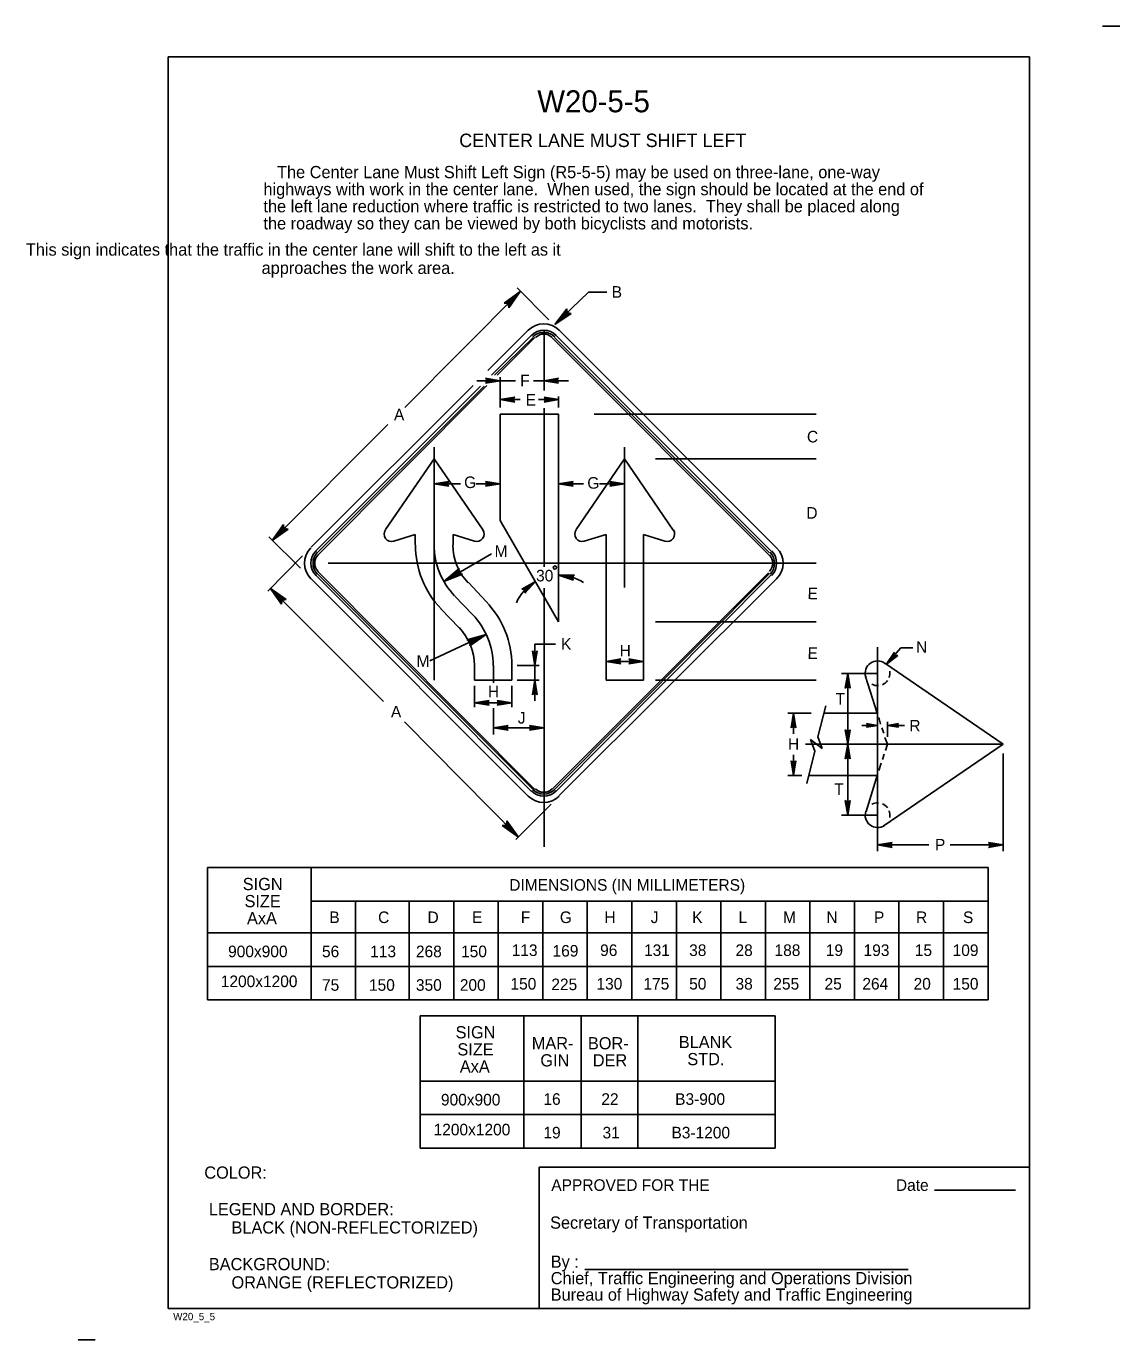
# Model space of a CAD drawing. Extents: x -0.029 to 0.195, y -0.006 to 0.263.
import ezdxf

# ---------------------------------------------------------------- set-up
doc = ezdxf.new("R2010")
doc.units = 0
for name, color, linetype in [('1', 7, 'Continuous'), ('2', 7, 'Continuous'), ('3', 7, 'Continuous')]:
    doc.layers.add(name, color=color, linetype=linetype)

# ---------------------------------------------------------------- blocks, each defined once
blk = doc.blocks.new('RARROW')
at = {"layer": '3'}
for p, q in [((-2.156, 0.28500000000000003), (-2.2665, 0.384625)), ((-2.2665, 0.384625), (0, 0)), ((0, 0), (-2.2665, -0.379125)), ((-2.156, 0.28500000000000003), (-2.075625, 0.12075)), ((0, 0), (-2.156, 0.28500000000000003)), ((-2.14975, -0.2705), (0, 0)), ((-2.075625, 0.12075), (0, 0)), ((0, 0), (-2.074, -0.108)), ((-2.2665, -0.379125), (-2.14975, -0.2705)), ((-2.074, -0.108), (-2.14975, -0.2705))]:
    blk.add_line(p, q, dxfattribs=at)

msp = doc.modelspace()

# ---------------------------------------------------------------- linework, layer by layer
at = {"layer": '1'}
for p, q in [((0.195, 0.26275), (0.1915, 0.26275)), ((0.1765, 0.2565), (0, 0.2565)), ((0, 0.2565), (0, 0)), ((0.1765, 0), (0.1765, 0.2565)), ((0.077, 0.20025), (0.077, 0.18812500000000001)), ((0.0795, 0.199375), (0.1235, 0.15525)), ((0.080125, 0.2005), (0.124625, 0.155875)), ((0.078625, 0.199), (0.123125, 0.154375)), ((0.079125, 0.199), (0.12325, 0.154875)), ((0.068, 0.18325), (0.08, 0.18325)), ((0.068, 0.18325), (0.068, 0.1615)), ((0.077, 0.1845), (0.077, 0.152)), ((0.08, 0.18325), (0.08, 0.14075000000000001)), ((0.0545, 0.12875), (0.0545, 0.1765)), ((0.0935, 0.14775), (0.0935, 0.1765)), ((0.0445, 0.15962500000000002), (0.0545, 0.174125)), ((0.0645, 0.1595), (0.0545, 0.174125)), ((0.083625, 0.15962500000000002), (0.0935, 0.174125)), ((0.10350000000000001, 0.1595), (0.0935, 0.174125)), ((0.068, 0.1615), (0.08, 0.14075000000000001)), ((0.04625, 0.15725), (0.050625, 0.15862500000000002)), ((0.050625, 0.1565), (0.050625, 0.15862500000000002)), ((0.06275, 0.15725), (0.058375, 0.15862500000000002)), ((0.058375, 0.1565), (0.058375, 0.15862500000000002)), ((0.08525, 0.15725), (0.08975, 0.15862500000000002)), ((0.08975, 0.12875), (0.08975, 0.15862500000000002)), ((0.10175000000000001, 0.15725), (0.097375, 0.15862500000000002)), ((0.097375, 0.12875), (0.097375, 0.15862500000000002)), ((0.030625, 0.151), (0.075125, 0.106375)), ((0.03275, 0.15275), (0.129125, 0.15275)), ((0.02925, 0.1495), (0.07375, 0.105)), ((0.03025, 0.15025), (0.074375, 0.106)), ((0.0305, 0.150625), (0.07475, 0.106375)), ((0.0615, 0.14875), (0.065125, 0.144875)), ((0.058750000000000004, 0.146), (0.062375, 0.14225000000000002)), ((0.077, 0.147625), (0.077, 0.094625)), ((0.055875, 0.143375), (0.059625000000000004, 0.1395)), ((0.145375, 0.1355), (0.145375, 0.097125)), ((0.146875, 0.13225), (0.171125, 0.115625)), ((0.06275, 0.13175), (0.06275, 0.12875)), ((0.066625, 0.13175), (0.066625, 0.12825)), ((0.07037500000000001, 0.13175), (0.07037500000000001, 0.12875)), ((0.142875, 0.1295), (0.14525, 0.122)), ((0.066625, 0.123), (0.066625, 0.11762500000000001)), ((0.13475, 0.1235), (0.133125, 0.117125)), ((0.134375, 0.122), (0.14525, 0.122)), ((0.145625, 0.121125), (0.146, 0.11975000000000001)), ((0.14625, 0.11900000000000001), (0.146625, 0.11787500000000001)), ((0.1325, 0.11425), (0.131625, 0.116625)), ((0.131625, 0.116625), (0.134, 0.11475)), ((0.134, 0.11475), (0.133125, 0.117125)), ((0.146875, 0.117), (0.147375, 0.115625)), ((0.130625, 0.115625), (0.171125, 0.115625)), ((0.1325, 0.11425), (0.130875, 0.107625)), ((0.146375, 0.1125), (0.14675, 0.113625)), ((0.14675, 0.099), (0.171125, 0.115625)), ((0.147, 0.114375), (0.147375, 0.115625)), ((0.145625, 0.11025), (0.146125, 0.11175)), ((0.13125, 0.10925), (0.14525, 0.10925)), ((0.14300000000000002, 0.10187500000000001), (0.14525, 0.10925)), ((0.076, 0.029), (0.1765, 0.029)), ((0.076, 0.029), (0.076, 0)), ((0.157, 0.02425), (0.173625, 0.02425)), ((0.085375, 0.008), (0.151625, 0.008)), ((0, 0), (0.1765, 0)), ((-0.015, -0.0063750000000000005), (-0.0185, -0.0063750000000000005))]:
    msp.add_line(p, q, dxfattribs=at)
for centre, radius, start, end in [((0.045770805, 0.15869167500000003), 0.00152, 143.78869166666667, 286.41078333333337), ((0.063210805, 0.15869167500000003), 0.00152, 251.56804722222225, 34.022558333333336), ((0.084810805, 0.15869167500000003), 0.00152, 143.78869166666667, 286.41078333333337), ((0.102250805, 0.15869167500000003), 0.00152, 251.56804722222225, 34.022558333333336), ((0.069530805, 0.15645167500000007), 0.01888, 180, 223.86679444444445), ((0.069530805, 0.15645167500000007), 0.015040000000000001, 180, 223.86679444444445), ((0.069530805, 0.15645167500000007), 0.011200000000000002, 180, 223.86686666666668), ((0.051530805, 0.13177167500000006), 0.01888, 0, 43.86675), ((0.051530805, 0.13177167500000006), 0.015040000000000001, 0, 43.866794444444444), ((0.051530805, 0.13177167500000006), 0.011200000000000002, 0, 43.866794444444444), ((0.1453589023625, 0.13016981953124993), 0.0025326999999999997, 53.788691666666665, 196.41078333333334), ((0.1453589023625, 0.13016981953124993), 0.0025326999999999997, 340.1148361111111, 10.505063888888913), ((0.1453589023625, 0.13016981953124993), 0.0025326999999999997, 242.24145833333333, 273.7748277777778), ((0.1453589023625, 0.13016981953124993), 0.0025326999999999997, 292.9782916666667, 323.56914166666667), ((0.1453589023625, 0.10111041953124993), 0.0025326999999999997, 86.22517222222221, 117.75854166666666), ((0.1453589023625, 0.10111041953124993), 0.0025326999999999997, 36.43085833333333, 67.02170833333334), ((0.1453589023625, 0.10111041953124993), 0.0025326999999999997, 161.56804722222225, 304.02255833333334), ((0.1453589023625, 0.10111041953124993), 0.0025326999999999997, 349.4949361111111, 19.88516388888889)]:
    msp.add_arc(centre, radius, start, end, dxfattribs=at)
at = {"layer": '3'}
for p, q in [((0.0485, 0.184625), (0.072125, 0.208375)), ((0.078, 0.202625), (0.07150000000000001, 0.209125)), ((0.078, 0.202625), (0.07150000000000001, 0.209125)), ((0.07925, 0.201625), (0.08612500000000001, 0.20825)), ((0.08612500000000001, 0.20825), (0.089875, 0.20825)), ((0.0655, 0.19225), (0.07375, 0.2005)), ((0.06625, 0.19125), (0.074375, 0.199375)), ((0.066875, 0.19125), (0.07475, 0.199)), ((0.067375, 0.19125), (0.075125, 0.199)), ((0.02925, 0.156), (0.0625, 0.18912500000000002)), ((0.03025, 0.15525), (0.064, 0.189)), ((0.0305, 0.154875), (0.06475, 0.189)), ((0.030625, 0.154375), (0.06525, 0.18912500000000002)), ((0.06325, 0.19012500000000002), (0.068, 0.19012500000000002)), ((0.068, 0.184625), (0.068, 0.19087500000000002)), ((0.07112500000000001, 0.19012500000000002), (0.068, 0.19012500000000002)), ((0.077, 0.19012500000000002), (0.074875, 0.19012500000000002)), ((0.077, 0.19087500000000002), (0.077, 0.18812500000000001)), ((0.077, 0.19012500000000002), (0.082, 0.19012500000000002)), ((0.072125, 0.18625), (0.068, 0.18625)), ((0.08, 0.18625), (0.075875, 0.18625)), ((0.08, 0.184625), (0.08, 0.186875)), ((0.08725000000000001, 0.18325), (0.13275, 0.18325)), ((0.045, 0.181125), (0.02125, 0.15737500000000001)), ((0.099875, 0.174125), (0.13275, 0.174125)), ((0.0545, 0.169), (0.059875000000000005, 0.169)), ((0.063, 0.169), (0.068, 0.169)), ((0.085125, 0.169), (0.08, 0.169)), ((0.0935, 0.169), (0.088375, 0.169)), ((0.027125, 0.15175), (0.020625, 0.15812500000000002)), ((0.0275, 0.15425), (0.020375, 0.147)), ((0.06625, 0.154625), (0.0565, 0.149)), ((0.07875, 0.1065), (0.123, 0.15075)), ((0.129125, 0.15275), (0.13275, 0.15275)), ((0.079125, 0.106375), (0.12325, 0.150625)), ((0.0795, 0.106), (0.1235, 0.15025)), ((0.080125, 0.105125), (0.124625, 0.1495)), ((0.044125, 0.124375), (0.020875, 0.147625)), ((0.099875, 0.14075000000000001), (0.13275, 0.14075000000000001)), ((0.053625, 0.13275), (0.065125, 0.138125)), ((0.075125, 0.136125), (0.075125, 0.13175)), ((0.075125, 0.136125), (0.079375, 0.136125)), ((0.147125, 0.132), (0.150125, 0.135375)), ((0.152625, 0.135375), (0.150125, 0.135375)), ((0.08975, 0.132625), (0.097375, 0.132625)), ((0.07150000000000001, 0.13175), (0.076, 0.13175)), ((0.075125, 0.13175), (0.075125, 0.12875)), ((0.138, 0.130125), (0.145375, 0.130125)), ((0.13925, 0.115625), (0.13925, 0.130125)), ((0.07037500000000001, 0.12875), (0.06275, 0.12875)), ((0.06275, 0.12762500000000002), (0.06275, 0.12325)), ((0.07037500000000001, 0.12762500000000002), (0.07037500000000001, 0.12325)), ((0.07150000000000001, 0.12875), (0.076, 0.12875)), ((0.075125, 0.12875), (0.075125, 0.1245)), ((0.08975, 0.12875), (0.097375, 0.12875)), ((0.099875, 0.12875), (0.13275, 0.12875)), ((0.06275, 0.124125), (0.07037500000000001, 0.124125)), ((0.127, 0.122), (0.13175, 0.122)), ((0.128125, 0.11775000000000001), (0.128125, 0.122)), ((0.048375, 0.12025), (0.07175000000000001, 0.096625)), ((0.066625, 0.11900000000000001), (0.077, 0.11900000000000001)), ((0.145375, 0.11950000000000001), (0.142125, 0.11950000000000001)), ((0.147375, 0.117125), (0.147375, 0.12025)), ((0.150875, 0.11950000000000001), (0.147375, 0.11950000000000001)), ((0.128125, 0.1135), (0.128125, 0.10925)), ((0.13925, 0.115625), (0.13925, 0.101125)), ((0.171125, 0.09375), (0.171125, 0.11375)), ((0.127, 0.10925), (0.129875, 0.10925)), ((0.0785, 0.10337500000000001), (0.07125000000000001, 0.096125)), ((0.138, 0.101125), (0.145375, 0.101125)), ((0.145375, 0.09375), (0.145375, 0.097125)), ((0.145375, 0.095), (0.155875, 0.095)), ((0.16025, 0.095), (0.171125, 0.095)), ((0.008, 0.090375), (0.168, 0.090375)), ((0.008, 0.090375), (0.008, 0.06325)), ((0.02925, 0.090375), (0.02925, 0.06325)), ((0.168, 0.090375), (0.168, 0.06325)), ((0.168, 0.0835), (0.02925, 0.0835)), ((0.038375, 0.0835), (0.038375, 0.06325)), ((0.049375, 0.0835), (0.049375, 0.06325)), ((0.0585, 0.0835), (0.0585, 0.06325)), ((0.067625, 0.0835), (0.067625, 0.06325)), ((0.07675, 0.0835), (0.07675, 0.06325)), ((0.085875, 0.0835), (0.085875, 0.06325)), ((0.095, 0.0835), (0.095, 0.06325)), ((0.104125, 0.0835), (0.104125, 0.06325)), ((0.11325, 0.0835), (0.11325, 0.06325)), ((0.122375, 0.0835), (0.122375, 0.06325)), ((0.1315, 0.0835), (0.1315, 0.06325)), ((0.140625, 0.0835), (0.140625, 0.06325)), ((0.14975, 0.0835), (0.14975, 0.06325)), ((0.15887500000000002, 0.0835), (0.15887500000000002, 0.06325)), ((0.008, 0.077), (0.168, 0.077)), ((0.008, 0.070125), (0.168, 0.070125)), ((0.008, 0.06325), (0.168, 0.06325)), ((0.051625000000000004, 0.06), (0.124375, 0.06)), ((0.051625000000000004, 0.06), (0.051625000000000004, 0.032875)), ((0.072875, 0.06), (0.072875, 0.032875)), ((0.072875, 0.06), (0.072875, 0.03975)), ((0.084625, 0.06), (0.084625, 0.032875)), ((0.09625, 0.06), (0.09625, 0.032875)), ((0.124375, 0.06), (0.124375, 0.032875)), ((0.051625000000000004, 0.046625), (0.124375, 0.046625)), ((0.051625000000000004, 0.03975), (0.124375, 0.03975)), ((0.051625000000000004, 0.032875), (0.124375, 0.032875))]:
    msp.add_line(p, q, dxfattribs=at)
msp.add_circle((0.0792320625, 0.1518385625), 0.00034737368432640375, dxfattribs=at)
for centre, radius, start, end in [((0.07695602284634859, 0.19727937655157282), 0.0044998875, 45, 135), ((0.07695602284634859, 0.19685512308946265), 0.003599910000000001, 45, 135), ((0.07695602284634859, 0.19685512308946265), 0.0031780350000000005, 45, 135), ((0.07695602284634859, 0.19727937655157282), 0.0023998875, 45, 135), ((0.0324090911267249, 0.15273244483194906), 0.0044998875, 135, 225), ((0.032833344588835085, 0.15273244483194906), 0.003599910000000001, 135, 225), ((0.032833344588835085, 0.15273244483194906), 0.0031780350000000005, 135, 225), ((0.0324090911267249, 0.15273244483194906), 0.0023998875, 135, 225), ((0.12150263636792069, 0.15273276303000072), 0.0023998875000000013, 315, 45), ((0.12107838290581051, 0.15273276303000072), 0.0031780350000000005, 315, 45), ((0.12107838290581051, 0.15273276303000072), 0.003599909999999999, 315, 45), ((0.12150263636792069, 0.15273276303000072), 0.004499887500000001, 315, 45), ((0.08001075, 0.140731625), 0.009504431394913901, 119.99356666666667, 155.97758333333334), ((0.08001075, 0.140731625), 0.009504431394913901, 57.56237777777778, 90), ((0.07695570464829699, 0.108185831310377), 0.004499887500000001, 225.00000000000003, 315), ((0.07695570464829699, 0.1086100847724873), 0.003599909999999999, 225.00000000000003, 315), ((0.07695570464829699, 0.1086100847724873), 0.0031780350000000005, 225.00000000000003, 315), ((0.07695570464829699, 0.108185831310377), 0.0023998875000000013, 225.00000000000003, 315)]:
    msp.add_arc(centre, radius, start, end, dxfattribs=at)

# ---------------------------------------------------------------- block references
for p, xscale, yscale, rotation in [((0.072125, 0.208375), 0.0017647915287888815, 0.0017457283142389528, 44.99999999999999), ((0.07925, 0.201625), 0.0017647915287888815, 0.001745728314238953, -136), ((0.077, 0.19012500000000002), 0.0013235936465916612, 0.0013092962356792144, 180), ((0.068, 0.18625), 0.0013235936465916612, 0.0013092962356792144, 180), ((0.0545, 0.169), 0.0013235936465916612, 0.0013092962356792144, 180), ((0.08, 0.169), 0.0013235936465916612, 0.0013092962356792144, 180), ((0.02125, 0.15737500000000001), 0.0017647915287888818, 0.0017457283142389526, -135.00000000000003), ((0.0565, 0.149), 0.0017647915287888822, 0.0017457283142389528, -148.99999999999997), ((0.08, 0.15025), 0.0014118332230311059, -0.0013965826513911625, 170.99999999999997), ((0.020875, 0.147625), 0.0017647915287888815, 0.0017457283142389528, 135), ((0.07525, 0.149), 0.001411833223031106, 0.0013965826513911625, 39.00000000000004), ((0.065125, 0.138125), 0.001764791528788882, 0.001745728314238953, 25.00000000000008), ((0.075125, 0.13175), 0.0013235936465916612, 0.0013092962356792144, -90.00000000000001), ((0.08975, 0.132625), 0.0013235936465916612, 0.0013092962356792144, 180), ((0.147125, 0.132), 0.0013235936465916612, -0.0013092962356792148, -132.99999999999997), ((0.13925, 0.130125), 0.0013235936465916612, -0.0013092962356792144, 90.00000000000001), ((0.075125, 0.12875), 0.0013235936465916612, -0.0013092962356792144, 90.00000000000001), ((0.06275, 0.124125), 0.0013235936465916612, 0.0013092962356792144, 180), ((0.128125, 0.122), 0.0013235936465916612, -0.0013092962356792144, 90.00000000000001), ((0.066625, 0.11900000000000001), 0.0013235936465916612, 0.0013092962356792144, 180), ((0.13925, 0.115625), 0.0013235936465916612, 0.0013092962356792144, -90.00000000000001), ((0.147375, 0.11950000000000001), 0.000992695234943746, 0.0009819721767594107, 180), ((0.13925, 0.115625), 0.0013235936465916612, -0.0013092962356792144, 90.00000000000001), ((0.128125, 0.10925), 0.0013235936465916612, 0.0013092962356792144, -90.00000000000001), ((0.13925, 0.101125), 0.0013235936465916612, 0.0013092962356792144, -90.00000000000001), ((0.07175000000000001, 0.096625), 0.0017647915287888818, 0.0017457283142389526, -45.00000000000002), ((0.145375, 0.095), 0.0013235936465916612, -0.0013092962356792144, -180)]:
    msp.add_blockref('RARROW', p, dxfattribs=dict(at, xscale=xscale, yscale=yscale, rotation=rotation))
for p, xscale, yscale in [((0.068, 0.19012500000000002), 0.0013235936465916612, -0.0013092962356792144), ((0.08, 0.18625), 0.0013235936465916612, -0.0013092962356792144), ((0.068, 0.169), 0.0013235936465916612, -0.0013092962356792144), ((0.0935, 0.169), 0.0013235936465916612, -0.0013092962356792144), ((0.097375, 0.132625), 0.0013235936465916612, -0.0013092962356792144), ((0.07037500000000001, 0.124125), 0.0013235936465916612, -0.0013092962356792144), ((0.077, 0.11900000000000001), 0.0013235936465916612, -0.0013092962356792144), ((0.145375, 0.11950000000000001), 0.000992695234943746, -0.0009819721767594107), ((0.171125, 0.095), 0.0013235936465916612, 0.0013092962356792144)]:
    msp.add_blockref('RARROW', p, dxfattribs=dict(at, xscale=xscale, yscale=yscale))

# ---------------------------------------------------------------- texts
at = {"layer": '1'}
for s, height, p in [('W20-5-5', 0.0045000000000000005, (0.075625, 0.245125)), ('CENTER LANE MUST SHIFT LEFT', 0.00275025, (0.059625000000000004, 0.23800000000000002)), ('COLOR:', 0.0024997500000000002, (0.0073750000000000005, 0.026625)), ('APPROVED FOR THE', 0.0023752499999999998, (0.0785, 0.024125)), ('Date ', 0.0023752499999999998, (0.149125, 0.024125)), (' LEGEND AND BORDER:', 0.0024997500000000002, (0.0073750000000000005, 0.019125)), ('Secretary of Transportation', 0.0024997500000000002, (0.07825, 0.016375)), ('      BLACK (NON-REFLECTORIZED)', 0.0024997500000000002, (0.0073750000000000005, 0.015375)), ('By :', 0.0024997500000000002, (0.078375, 0.008375)), (' BACKGROUND:', 0.0024997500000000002, (0.0073750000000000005, 0.007875)), ('      ORANGE (REFLECTORIZED)', 0.0024997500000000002, (0.0073750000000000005, 0.004125)), ('Chief, Traffic Engineering and Operations Division', 0.0024997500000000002, (0.078375, 0.005)), ('Bureau of Highway Safety and Traffic Engineering', 0.0024997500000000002, (0.078375, 0.0016250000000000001)), ('W20_5_5', 0.0015, (0.001, -0.002375))]:
    msp.add_text(s, height=height, dxfattribs=at).set_placement(p)
at = {"layer": '2'}
for s, p in [('   The Center Lane Must Shift Left Sign (R5-5-5) may be used on three-lane, one-way', (0.0195, 0.231625)), ('highways with work in the center lane.  When used, the sign should be located at the end of', (0.0195, 0.228125)), ('the left lane reduction where traffic is restricted to two lanes.  They shall be placed along ', (0.0195, 0.224625)), ('the roadway so they can be viewed by both bicyclists and motorists.', (0.0195, 0.22112500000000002))]:
    msp.add_text(s, height=0.0024997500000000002, dxfattribs=at).set_placement(p)
at = {"layer": '3'}
for s, height, p in [('                                    This sign indicates that the traffic in the center lane will shift to the left as it', 0.0024997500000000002, (-0.062625, 0.21575)), ('approaches the work area.', 0.0024997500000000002, (0.019125, 0.212)), ('B', 0.0023737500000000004, (0.090875, 0.207125)), ('F', 0.0023737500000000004, (0.072125, 0.189)), ('E', 0.0023737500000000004, (0.07325, 0.185)), ('A', 0.0023745, (0.04625, 0.182)), ('G', 0.0023745, (0.060625, 0.168125)), ('G', 0.0023745, (0.085875, 0.168)), ('M', 0.0023745, (0.066875, 0.154)), ('30', 0.0023737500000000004, (0.075375, 0.149)), ('K', 0.0023737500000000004, (0.0805, 0.135)), ('H', 0.0023737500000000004, (0.0925, 0.133625)), ('N', 0.0023737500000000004, (0.15325, 0.134375)), ('M', 0.0023745, (0.050875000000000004, 0.1315)), ('H', 0.0023737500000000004, (0.0655, 0.12525)), ('T', 0.0023737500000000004, (0.13675, 0.12375)), ('A', 0.0023745, (0.045625, 0.121125)), ('J', 0.0023737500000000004, (0.07162500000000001, 0.11987500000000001)), ('R', 0.0023737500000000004, (0.151875, 0.11825000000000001)), ('H', 0.0023737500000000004, (0.127, 0.1145)), ('T', 0.0023737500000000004, (0.1365, 0.10525)), ('P', 0.0023737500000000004, (0.15712500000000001, 0.093875)), ('SIGN', 0.0024997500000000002, (0.01525, 0.08575)), ('DIMENSIONS (IN MILLIMETERS)', 0.0023752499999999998, (0.069875, 0.085625)), ('SIZE', 0.0024997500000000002, (0.015625, 0.08225)), ('AxA', 0.0024997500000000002, (0.016125, 0.07875)), ('B', 0.0023752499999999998, (0.033, 0.079)), ('C', 0.0023752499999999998, (0.043000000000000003, 0.079)), ('D', 0.0023752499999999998, (0.053125, 0.079)), ('E', 0.0023752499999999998, (0.06225, 0.079)), ('F', 0.0023752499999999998, (0.07225, 0.079)), ('G', 0.0023752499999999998, (0.08025, 0.079)), ('H', 0.0023752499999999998, (0.089375, 0.079)), ('J', 0.0023752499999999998, (0.098875, 0.079)), ('K', 0.0023752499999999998, (0.107375, 0.079)), ('L', 0.0023752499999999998, (0.116875, 0.079)), ('M', 0.0023752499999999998, (0.126, 0.079)), ('N', 0.0023752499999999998, (0.134875, 0.079)), ('P', 0.0023752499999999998, (0.144625, 0.079)), ('R', 0.0023752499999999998, (0.15325, 0.079)), ('S', 0.0023752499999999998, (0.162875, 0.079)), ('900x900', 0.0023752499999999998, (0.01225, 0.07200000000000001)), ('56', 0.0023752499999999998, (0.0315, 0.07200000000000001)), ('113', 0.0023752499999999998, (0.041375, 0.07200000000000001)), ('268', 0.0023752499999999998, (0.05075, 0.07200000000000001)), ('150', 0.0023752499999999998, (0.06, 0.07200000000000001)), ('113', 0.0023752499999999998, (0.07037500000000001, 0.07225)), ('169', 0.0023752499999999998, (0.07875, 0.072125)), ('96', 0.0023752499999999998, (0.0885, 0.07225)), ('131', 0.0023752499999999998, (0.0975, 0.07225)), ('38', 0.0023752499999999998, (0.10675, 0.07225)), ('28', 0.0023752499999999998, (0.11625, 0.07225)), ('188', 0.0023752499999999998, (0.12425, 0.07225)), ('19', 0.0023752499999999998, (0.13475, 0.07225)), ('193', 0.0023752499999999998, (0.14250000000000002, 0.07225)), ('15', 0.0023752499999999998, (0.153, 0.07225)), ('109', 0.0023752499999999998, (0.16075, 0.07225)), ('1200x1200', 0.0023752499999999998, (0.010750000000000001, 0.065875)), ('75', 0.0023752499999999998, (0.0315, 0.065125)), ('150', 0.0023752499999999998, (0.041125, 0.065125)), ('350', 0.0023752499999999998, (0.05075, 0.065125)), ('200', 0.0023752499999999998, (0.059750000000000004, 0.065125)), ('150', 0.0023752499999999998, (0.070125, 0.065375)), ('225', 0.0023752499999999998, (0.0785, 0.06525)), ('130', 0.0023752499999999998, (0.08775000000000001, 0.065375)), ('175', 0.0023752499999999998, (0.097375, 0.065375)), ('50', 0.0023752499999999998, (0.10675, 0.065375)), ('38', 0.0023752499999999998, (0.11625, 0.065375)), ('255', 0.0023752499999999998, (0.124, 0.065375)), ('25', 0.0023752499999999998, (0.1345, 0.065375)), ('264', 0.0023752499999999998, (0.14225000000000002, 0.065375)), ('20', 0.0023752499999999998, (0.15275, 0.065375)), ('150', 0.0023752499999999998, (0.16075, 0.065375)), ('SIGN', 0.0024997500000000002, (0.058875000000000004, 0.055375)), ('SIZE', 0.0024997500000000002, (0.059250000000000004, 0.051875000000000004)), ('MAR-', 0.0024997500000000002, (0.0745, 0.053125)), ('BOR-', 0.0024997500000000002, (0.08600000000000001, 0.053125)), ('BLANK', 0.0024997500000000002, (0.104625, 0.053375)), ('GIN', 0.0024997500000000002, (0.07625, 0.049625)), ('DER', 0.0024997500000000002, (0.08700000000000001, 0.049625)), ('STD.', 0.0024997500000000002, (0.106375, 0.049875)), ('AxA', 0.0024997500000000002, (0.059750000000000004, 0.048375)), ('900x900', 0.0023752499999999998, (0.055875, 0.041625)), ('16', 0.0023752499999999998, (0.076875, 0.04175)), ('22', 0.0023752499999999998, (0.08875, 0.04175)), ('B3-900', 0.0023752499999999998, (0.10387500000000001, 0.04175)), ('1200x1200', 0.0023752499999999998, (0.054375, 0.035500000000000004)), ('19', 0.0023752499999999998, (0.076875, 0.034875)), ('31', 0.0023752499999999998, (0.089, 0.034875)), ('B3-1200', 0.0023752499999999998, (0.10312500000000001, 0.034875))]:
    msp.add_text(s, height=height, dxfattribs=at).set_placement(p)
for s, p in [('C', (0.130875, 0.1775)), ('D', (0.13075, 0.161875)), ('E', (0.131, 0.145375)), ('E', (0.131, 0.133125))]:
    msp.add_text(s, height=0.0023737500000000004, rotation=359, dxfattribs=at).set_placement(p)

doc.saveas('drawing.dxf')
